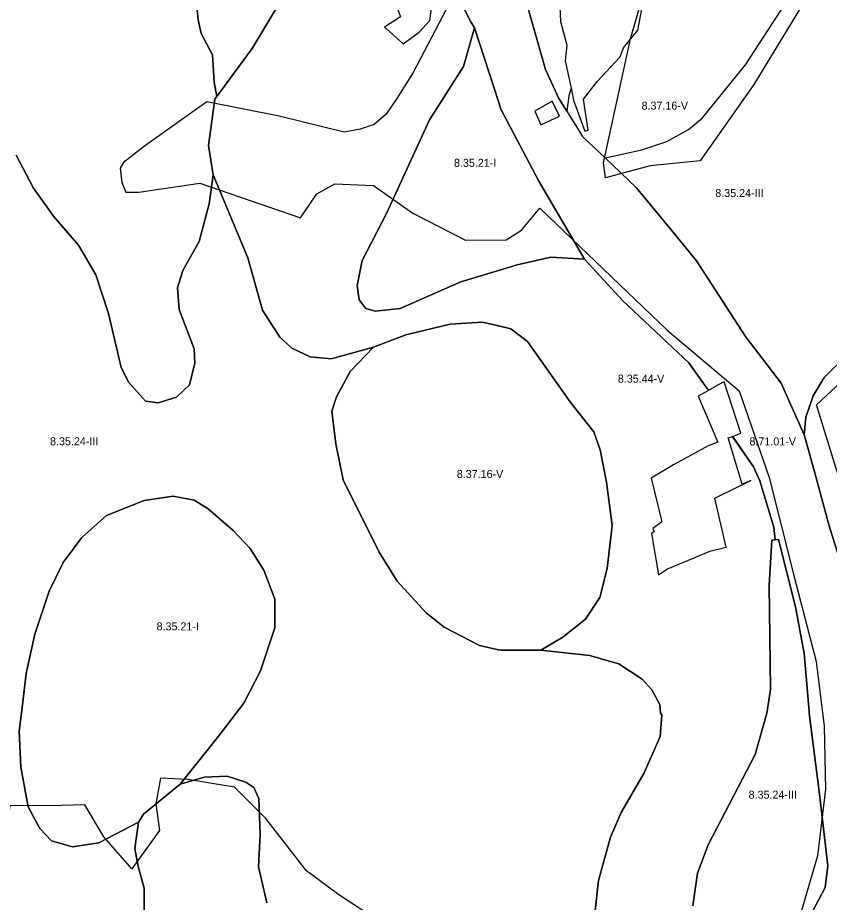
# Model space of a CAD drawing. Extents: x -547623 to -533936, y -1096714 to -1086523.
# Drawn here: x -541850 to -540837, y -1093236 to -1092131 of the extents above; entities that cross this region are included whole.
import ezdxf

# ---------------------------------------------------------------- set-up
doc = ezdxf.new("R2010")
doc.units = 0
for name, color, linetype in [('Vrstva 27', 7, 'Continuous'), ('Vrstva 28', 7, 'Continuous'), ('Vrstva 29', 7, 'Continuous')]:
    doc.layers.add(name, color=color, linetype=linetype)

msp = doc.modelspace()

# ---------------------------------------------------------------- linework, layer by layer
at = {"layer": 'Vrstva 28'}
for p, q in [((-541310.5, -1092085), (-541284.5, -1092136.5)), ((-541629, -1092091), (-541625, -1092134)), ((-541557.5, -1092170), (-541525, -1092116)), ((-541625, -1092134), (-541621, -1092151)), ((-541284.5, -1092136.5), (-541280, -1092144)), ((-541621, -1092151), (-541607, -1092178)), ((-541293.5, -1092192.5), (-541280, -1092144)), ((-541280, -1092144), (-541293.5, -1092192.5)), ((-541280, -1092144), (-541250, -1092236.3)), ((-541601.5, -1092230), (-541557.5, -1092170)), ((-541607, -1092178), (-541605, -1092212)), ((-541336, -1092259), (-541293.5, -1092192.5)), ((-541293.5, -1092192.5), (-541336, -1092259)), ((-541605, -1092212), (-541601.5, -1092230)), ((-541601.5, -1092230), (-541604, -1092233)), ((-541604, -1092233), (-541601.5, -1092230)), ((-541604, -1092233), (-541612, -1092291)), ((-541612, -1092291), (-541604, -1092233)), ((-541250, -1092236.3), (-541247, -1092245.5)), ((-541247, -1092245.5), (-541199.5, -1092335.5)), ((-541389.5, -1092376), (-541336, -1092259)), ((-541336, -1092259), (-541389.5, -1092376)), ((-541612, -1092291), (-541606, -1092327.5)), ((-541606, -1092327.5), (-541612, -1092291)), ((-541830.5, -1092344.5), (-541852, -1092303)), ((-541852, -1092303), (-541830.5, -1092344.5)), ((-541606, -1092327.5), (-541611, -1092364)), ((-541611, -1092364), (-541606, -1092327.5)), ((-541606, -1092327.5), (-541563, -1092431.5)), ((-541563, -1092431.5), (-541606, -1092327.5)), ((-541199.5, -1092335.5), (-541142.5, -1092433)), ((-541805.5, -1092379.5), (-541830.5, -1092344.5)), ((-541830.5, -1092344.5), (-541805.5, -1092379.5)), ((-541611, -1092364), (-541623.5, -1092411)), ((-541623.5, -1092411), (-541611, -1092364)), ((-541774.5, -1092415.5), (-541805.5, -1092379.5)), ((-541805.5, -1092379.5), (-541774.5, -1092415.5)), ((-541420, -1092434.5), (-541389.5, -1092376)), ((-541389.5, -1092376), (-541420, -1092434.5)), ((-541752.5, -1092452.5), (-541774.5, -1092415.5)), ((-541774.5, -1092415.5), (-541752.5, -1092452.5)), ((-541623.5, -1092411), (-541644, -1092447)), ((-541644, -1092447), (-541623.5, -1092411)), ((-541563, -1092431.5), (-541544.5, -1092496.5)), ((-541544.5, -1092496.5), (-541563, -1092431.5)), ((-541426.5, -1092466), (-541420, -1092434.5)), ((-541420, -1092434.5), (-541426.5, -1092466)), ((-541226.5, -1092440), (-541250, -1092447.2)), ((-541250, -1092447.2), (-541226.5, -1092440)), ((-541184.5, -1092430.5), (-541226.5, -1092440)), ((-541226.5, -1092440), (-541184.5, -1092430.5)), ((-541142.5, -1092433), (-541184.5, -1092430.5)), ((-541184.5, -1092430.5), (-541142.5, -1092433)), ((-541142.5, -1092433), (-541095, -1092484.5)), ((-541644, -1092447), (-541650.5, -1092469)), ((-541650.5, -1092469), (-541644, -1092447)), ((-541250, -1092447.2), (-541297, -1092461.5)), ((-541297, -1092461.5), (-541250, -1092447.2)), ((-541737, -1092501), (-541752.5, -1092452.5)), ((-541752.5, -1092452.5), (-541737, -1092501)), ((-541297, -1092461.5), (-541372.5, -1092494.5)), ((-541372.5, -1092494.5), (-541297, -1092461.5)), ((-541650.5, -1092469), (-541648.5, -1092496)), ((-541648.5, -1092496), (-541650.5, -1092469)), ((-541424, -1092484), (-541426.5, -1092466)), ((-541426.5, -1092466), (-541424, -1092484)), ((-541415.5, -1092494.5), (-541424, -1092484)), ((-541424, -1092484), (-541415.5, -1092494.5)), ((-541404, -1092498), (-541415.5, -1092494.5)), ((-541415.5, -1092494.5), (-541404, -1092498)), ((-541372.5, -1092494.5), (-541404, -1092498)), ((-541404, -1092498), (-541372.5, -1092494.5)), ((-541095, -1092484.5), (-541012, -1092562.5)), ((-541721, -1092568.5), (-541737, -1092501)), ((-541737, -1092501), (-541721, -1092568.5)), ((-541648.5, -1092496), (-541630, -1092545)), ((-541630, -1092545), (-541648.5, -1092496)), ((-541544.5, -1092496.5), (-541523, -1092530.5)), ((-541523, -1092530.5), (-541544.5, -1092496.5)), ((-541310, -1092514), (-541365.5, -1092527.5)), ((-541365.5, -1092527.5), (-541310, -1092514)), ((-541270, -1092511.5), (-541310, -1092514)), ((-541310, -1092514), (-541270, -1092511.5)), ((-541250, -1092516.3), (-541270, -1092511.5)), ((-541270, -1092511.5), (-541250, -1092516.3)), ((-541234.5, -1092520), (-541250, -1092516.3)), ((-541250, -1092516.3), (-541234.5, -1092520)), ((-541365.5, -1092527.5), (-541406, -1092543)), ((-541406, -1092543), (-541365.5, -1092527.5)), ((-541213.5, -1092536), (-541234.5, -1092520)), ((-541234.5, -1092520), (-541213.5, -1092536)), ((-541523, -1092530.5), (-541508, -1092544)), ((-541508, -1092544), (-541523, -1092530.5)), ((-541159.5, -1092612.5), (-541213.5, -1092536)), ((-541213.5, -1092536), (-541159.5, -1092612.5)), ((-541630, -1092545), (-541629, -1092563)), ((-541629, -1092563), (-541630, -1092545)), ((-541508, -1092544), (-541485, -1092555)), ((-541485, -1092555), (-541508, -1092544)), ((-541459, -1092557.5), (-541406, -1092543)), ((-541406, -1092543), (-541459, -1092557.5)), ((-541406, -1092543), (-541435, -1092573.5)), ((-541435, -1092573.5), (-541406, -1092543)), ((-541485, -1092555), (-541459, -1092557.5)), ((-541459, -1092557.5), (-541485, -1092555)), ((-540843, -1092581), (-540816, -1092554)), ((-541711.5, -1092587), (-541721, -1092568.5)), ((-541721, -1092568.5), (-541711.5, -1092587)), ((-541629, -1092563), (-541635.5, -1092590)), ((-541635.5, -1092590), (-541629, -1092563)), ((-541012, -1092562.5), (-540987.8, -1092596.9)), ((-541435, -1092573.5), (-541452, -1092605)), ((-541452, -1092605), (-541435, -1092573.5)), ((-540857, -1092603.5), (-540843, -1092581)), ((-541690.5, -1092610.5), (-541711.5, -1092587)), ((-541711.5, -1092587), (-541690.5, -1092610.5)), ((-541635.5, -1092590), (-541652, -1092605.5)), ((-541652, -1092605.5), (-541635.5, -1092590)), ((-541652, -1092605.5), (-541675, -1092612.5)), ((-541675, -1092612.5), (-541652, -1092605.5)), ((-541452, -1092605), (-541458, -1092623)), ((-541458, -1092623), (-541452, -1092605)), ((-540866, -1092630.5), (-540857, -1092603.5)), ((-541675, -1092612.5), (-541690.5, -1092610.5)), ((-541690.5, -1092610.5), (-541675, -1092612.5)), ((-541131, -1092648.5), (-541159.5, -1092612.5)), ((-541159.5, -1092612.5), (-541131, -1092648.5)), ((-541458, -1092623), (-541453, -1092663.5)), ((-541453, -1092663.5), (-541458, -1092623)), ((-540868, -1092652.5), (-540866, -1092630.5)), ((-541123, -1092671), (-541131, -1092648.5)), ((-541131, -1092648.5), (-541123, -1092671)), ((-540957, -1092655.4), (-540931.5, -1092692.5)), ((-540866.8, -1092656.7), (-540868, -1092652.5)), ((-540855.5, -1092697), (-540866.8, -1092656.7)), ((-541453, -1092663.5), (-541444, -1092708.5)), ((-541444, -1092708.5), (-541453, -1092663.5)), ((-541115, -1092711.5), (-541123, -1092671)), ((-541123, -1092671), (-541115, -1092711.5)), ((-540931.5, -1092692.5), (-540923.5, -1092710)), ((-540837, -1092766), (-540855.5, -1092697)), ((-541444, -1092708.5), (-541399, -1092799)), ((-541399, -1092799), (-541444, -1092708.5)), ((-541108, -1092765.5), (-541115, -1092711.5)), ((-541115, -1092711.5), (-541108, -1092765.5)), ((-540923.5, -1092710), (-540906, -1092767.5)), ((-541739.5, -1092753), (-541692.5, -1092734.5)), ((-541692.5, -1092734.5), (-541739.5, -1092753)), ((-541692.5, -1092734.5), (-541656, -1092729)), ((-541656, -1092729), (-541692.5, -1092734.5)), ((-541656, -1092729), (-541630, -1092734)), ((-541630, -1092734), (-541656, -1092729)), ((-541630, -1092734), (-541612.5, -1092745)), ((-541612.5, -1092745), (-541630, -1092734)), ((-541612.5, -1092745), (-541581, -1092772)), ((-541581, -1092772), (-541612.5, -1092745)), ((-541770.5, -1092781), (-541739.5, -1092753)), ((-541739.5, -1092753), (-541770.5, -1092781)), ((-541114, -1092819.5), (-541108, -1092765.5)), ((-541108, -1092765.5), (-541114, -1092819.5)), ((-540906, -1092767.5), (-540904.5, -1092783.6)), ((-540798, -1092891.5), (-540837, -1092766)), ((-541793.5, -1092812), (-541770.5, -1092781)), ((-541770.5, -1092781), (-541793.5, -1092812)), ((-541581, -1092772), (-541560, -1092794.5)), ((-541560, -1092794.5), (-541581, -1092772)), ((-540912, -1092840), (-540908.5, -1092784)), ((-540908.5, -1092784), (-540912, -1092840)), ((-540908.5, -1092784), (-540904.5, -1092783.5)), ((-540904.5, -1092783.5), (-540908.5, -1092784)), ((-540904.5, -1092783.5), (-540900, -1092783)), ((-540900, -1092783), (-540879, -1092867)), ((-541560, -1092794.5), (-541543, -1092821.5)), ((-541543, -1092821.5), (-541560, -1092794.5)), ((-541399, -1092799), (-541376.5, -1092835)), ((-541376.5, -1092835), (-541399, -1092799)), ((-541811, -1092847.5), (-541793.5, -1092812)), ((-541793.5, -1092812), (-541811, -1092847.5)), ((-541543, -1092821.5), (-541529, -1092857.5)), ((-541529, -1092857.5), (-541543, -1092821.5)), ((-541123.5, -1092855.5), (-541114, -1092819.5)), ((-541114, -1092819.5), (-541123.5, -1092855.5)), ((-541376.5, -1092835), (-541340, -1092874.5)), ((-541340, -1092874.5), (-541376.5, -1092835)), ((-541829, -1092901.5), (-541811, -1092847.5)), ((-541811, -1092847.5), (-541829, -1092901.5)), ((-540910, -1092970.5), (-540912, -1092840)), ((-540912, -1092840), (-540910, -1092970.5)), ((-541529, -1092857.5), (-541529, -1092893.5)), ((-541529, -1092893.5), (-541529, -1092857.5)), ((-541141, -1092882.5), (-541123.5, -1092855.5)), ((-541123.5, -1092855.5), (-541141, -1092882.5)), ((-540879, -1092867), (-540868, -1092925.5)), ((-541340, -1092874.5), (-541317.5, -1092892.5)), ((-541317.5, -1092892.5), (-541340, -1092874.5)), ((-541317.5, -1092892.5), (-541273.5, -1092915.5)), ((-541273.5, -1092915.5), (-541317.5, -1092892.5)), ((-541169.5, -1092905), (-541141, -1092882.5)), ((-541141, -1092882.5), (-541169.5, -1092905)), ((-541839.5, -1092950.5), (-541829, -1092901.5)), ((-541829, -1092901.5), (-541839.5, -1092950.5)), ((-541529, -1092893.5), (-541547, -1092947)), ((-541547, -1092947), (-541529, -1092893.5)), ((-541197, -1092921.5), (-541169.5, -1092905)), ((-541169.5, -1092905), (-541197, -1092921.5)), ((-541273.5, -1092915.5), (-541250, -1092920.8)), ((-541250, -1092920.8), (-541273.5, -1092915.5)), ((-541250, -1092920.8), (-541247, -1092921.5)), ((-541247, -1092921.5), (-541250, -1092920.8)), ((-541247, -1092921.5), (-541197, -1092921.5)), ((-541197, -1092921.5), (-541247, -1092921.5)), ((-541197, -1092921.5), (-541136, -1092928)), ((-541136, -1092928), (-541197, -1092921.5)), ((-540868, -1092925.5), (-540862, -1092997.5)), ((-541136, -1092928), (-541099.5, -1092938.5)), ((-541099.5, -1092938.5), (-541136, -1092928)), ((-541547, -1092947), (-541568, -1092987.5)), ((-541568, -1092987.5), (-541547, -1092947)), ((-541099.5, -1092938.5), (-541070.5, -1092957.5)), ((-541070.5, -1092957.5), (-541099.5, -1092938.5)), ((-541845.7, -1093000), (-541839.5, -1092950.5)), ((-541839.5, -1092950.5), (-541845.7, -1093000)), ((-541070.5, -1092957.5), (-541058.5, -1092971)), ((-541058.5, -1092971), (-541070.5, -1092957.5)), ((-540914.7, -1093000), (-540910, -1092970.5)), ((-540910, -1092970.5), (-540914.7, -1093000)), ((-541058.5, -1092971), (-541048.5, -1092989)), ((-541048.5, -1092989), (-541058.5, -1092971)), ((-541568, -1092987.5), (-541577.5, -1093000)), ((-541577.5, -1093000), (-541568, -1092987.5)), ((-541048.5, -1092989), (-541047.5, -1093000)), ((-541047.5, -1093000), (-541048.5, -1092989)), ((-541848.5, -1093022.5), (-541845.7, -1093000)), ((-541845.7, -1093000), (-541848.5, -1093022.5)), ((-541577.5, -1093000), (-541599, -1093028.5)), ((-541599, -1093028.5), (-541577.5, -1093000)), ((-541046, -1093002.5), (-541048, -1093029)), ((-541048, -1093029), (-541046, -1093002.5)), ((-541047.5, -1093000), (-541046, -1093002.5)), ((-541046, -1093002.5), (-541047.5, -1093000)), ((-540929.5, -1093051.5), (-540914.7, -1093000)), ((-540914.7, -1093000), (-540929.5, -1093051.5)), ((-540862, -1092997.5), (-540861.7, -1093000)), ((-540861.7, -1093000), (-540849, -1093101)), ((-541846.5, -1093067.5), (-541848.5, -1093022.5)), ((-541848.5, -1093022.5), (-541846.5, -1093067.5)), ((-541599, -1093028.5), (-541647.5, -1093088.5)), ((-541647.5, -1093088.5), (-541599, -1093028.5)), ((-541048, -1093029), (-541068, -1093074.5)), ((-541068, -1093074.5), (-541048, -1093029)), ((-540988, -1093164.5), (-540929.5, -1093051.5)), ((-540929.5, -1093051.5), (-540988, -1093164.5)), ((-541837, -1093117), (-541846.5, -1093067.5)), ((-541846.5, -1093067.5), (-541837, -1093117)), ((-541617.5, -1093080), (-541647.5, -1093088.5)), ((-541647.5, -1093088.5), (-541617.5, -1093080)), ((-541588.5, -1093078.5), (-541617.5, -1093080)), ((-541617.5, -1093080), (-541588.5, -1093078.5)), ((-541565.5, -1093086), (-541588.5, -1093078.5)), ((-541588.5, -1093078.5), (-541565.5, -1093086)), ((-541068, -1093074.5), (-541096.5, -1093124)), ((-541096.5, -1093124), (-541068, -1093074.5)), ((-541647.5, -1093088.5), (-541693, -1093126)), ((-541693, -1093126), (-541647.5, -1093088.5)), ((-541555.5, -1093093), (-541565.5, -1093086)), ((-541565.5, -1093086), (-541555.5, -1093093)), ((-541549, -1093106.5), (-541555.5, -1093093)), ((-541555.5, -1093093), (-541549, -1093106.5)), ((-540849, -1093101), (-540838.5, -1093190.5)), ((-541547.5, -1093151.5), (-541549, -1093106.5)), ((-541549, -1093106.5), (-541547.5, -1093151.5)), ((-541822.5, -1093144), (-541837, -1093117)), ((-541837, -1093117), (-541822.5, -1093144)), ((-541096.5, -1093124), (-541110, -1093155)), ((-541110, -1093155), (-541096.5, -1093124)), ((-541699.5, -1093136), (-541749, -1093162)), ((-541749, -1093162), (-541699.5, -1093136)), ((-541699.5, -1093136), (-541704, -1093169)), ((-541704, -1093169), (-541699.5, -1093136)), ((-541693, -1093126), (-541699.5, -1093136)), ((-541699.5, -1093136), (-541693, -1093126)), ((-541808, -1093159.5), (-541822.5, -1093144)), ((-541822.5, -1093144), (-541808, -1093159.5)), ((-541549.5, -1093192), (-541547.5, -1093151.5)), ((-541547.5, -1093151.5), (-541549.5, -1093192)), ((-541110, -1093155), (-541125, -1093209)), ((-541125, -1093209), (-541110, -1093155)), ((-541782, -1093167), (-541808, -1093159.5)), ((-541808, -1093159.5), (-541782, -1093167)), ((-541749, -1093162), (-541782, -1093167)), ((-541782, -1093167), (-541749, -1093162)), ((-541704, -1093169), (-541700, -1093191.5)), ((-541700, -1093191.5), (-541704, -1093169)), ((-541001.5, -1093200), (-540988, -1093164.5)), ((-540988, -1093164.5), (-541001.5, -1093200)), ((-540838.5, -1093190.5), (-540842, -1093217.5)), ((-541700, -1093191.5), (-541692.5, -1093218.5)), ((-541692.5, -1093218.5), (-541700, -1093191.5)), ((-541539, -1093237), (-541549.5, -1093192)), ((-541549.5, -1093192), (-541539, -1093237)), ((-541007, -1093240.5), (-541001.5, -1093200)), ((-541001.5, -1093200), (-541007, -1093240.5)), ((-541125, -1093209), (-541133, -1093280.5)), ((-541133, -1093280.5), (-541125, -1093209)), ((-541692.5, -1093218.5), (-541692.5, -1093259)), ((-541692.5, -1093259), (-541692.5, -1093218.5)), ((-540842, -1093217.5), (-540901, -1093330))]:
    msp.add_line(p, q, dxfattribs=at)
for points in [[(-541325, -1092027.3), (-541382.1, -1092029.9), (-541401.5, -1092051.3), (-541372.3, -1092130.2), (-541392, -1092143.1), (-541390, -1092144.9), (-541368.7, -1092164), (-541349.1, -1092149.6), (-541335.6, -1092135.1), (-541332.8, -1092113.8), (-541334.3, -1092107.7), (-541320.2, -1092097.8), (-541313.2, -1092064.2), (-541308.1, -1092026.5), (-541325, -1092027.3)], [(-540990.6, -1092592.9), (-541012, -1092562.5), (-541095, -1092484.5), (-541142.5, -1092433), (-541199.5, -1092335.5), (-541247, -1092245.5), (-541250, -1092236.3), (-541280, -1092144), (-541284.5, -1092136.5), (-541310.5, -1092085), (-541315, -1092072.5)], [(-540816, -1092554), (-540843, -1092581), (-540857, -1092603.5), (-540866, -1092630.5), (-540868, -1092652.5), (-540897, -1092588), (-540941.5, -1092529.5), (-541002.5, -1092435), (-541032, -1092399), (-541078, -1092343.5), (-541116.5, -1092306.5), (-541071, -1092296.5), (-541039.5, -1092286), (-541012.5, -1092271), (-540995, -1092256.5), (-540941.5, -1092190.5), (-540895.5, -1092120), (-540873.5, -1092090), (-540869.1, -1092084.1)], [(-541852, -1092303), (-541830.5, -1092344.5), (-541805.5, -1092379.5), (-541774.5, -1092415.5), (-541752.5, -1092452.5), (-541737, -1092501), (-541721, -1092568.5), (-541711.5, -1092587), (-541690.5, -1092610.5), (-541675, -1092612.5), (-541652, -1092605.5), (-541635.5, -1092590), (-541629, -1092563), (-541630, -1092545), (-541648.5, -1092496), (-541650.5, -1092469), (-541644, -1092447), (-541623.5, -1092411), (-541611, -1092364), (-541606, -1092327.5), (-541612, -1092291), (-541604, -1092233), (-541601.5, -1092230), (-541605, -1092212), (-541607, -1092178), (-541621, -1092151), (-541625, -1092134), (-541629, -1092091)], [(-541525, -1092116), (-541557.5, -1092170), (-541601.5, -1092230), (-541605, -1092212), (-541607, -1092178), (-541621, -1092151), (-541625, -1092134), (-541629, -1092091)], [(-541218, -1092102), (-541191, -1092196), (-541174.5, -1092232.5), (-541164.5, -1092248), (-541145, -1092280), (-541116.5, -1092306.5), (-541078, -1092343.5), (-541032, -1092399), (-541002.5, -1092435), (-540941.5, -1092529.5), (-540897, -1092588), (-540868, -1092652.5), (-540866.8, -1092656.7), (-540855.5, -1092697), (-540837, -1092766), (-540798, -1092891.5)], [(-541159.3, -1092219.4), (-541162, -1092229), (-541164.5, -1092248), (-541174.5, -1092232.5), (-541191, -1092196), (-541218, -1092102)], [(-541173.1, -1092118.4), (-541172.6, -1092136.1), (-541164.6, -1092165.6), (-541166.8, -1092185.2), (-541159.3, -1092219.4)], [(-541159.3, -1092219.4), (-541156, -1092234.4), (-541142.1, -1092273.3), (-541137.7, -1092272.1), (-541143.6, -1092233.3), (-541126.5, -1092211.1), (-541097.9, -1092180.2), (-541093.8, -1092168.9), (-541075.8, -1092147.2), (-541070.9, -1092120.8), (-541068.1, -1092120.7)], [(-541336, -1092259), (-541389.5, -1092376), (-541420, -1092434.5), (-541426.5, -1092466), (-541424, -1092484), (-541415.5, -1092494.5), (-541404, -1092498), (-541372.5, -1092494.5), (-541297, -1092461.5), (-541250, -1092447.2), (-541226.5, -1092440), (-541184.5, -1092430.5), (-541142.5, -1092433), (-541199.5, -1092335.5), (-541247, -1092245.5), (-541250, -1092236.3), (-541280, -1092144), (-541293.5, -1092192.5), (-541336, -1092259)], [(-541197.1, -1092265.4), (-541173.8, -1092254.6), (-541182.9, -1092235.8), (-541204.6, -1092248.2), (-541197.1, -1092265.4)], [(-541133, -1093280.5), (-541125, -1093209), (-541110, -1093155), (-541096.5, -1093124), (-541068, -1093074.5), (-541048, -1093029), (-541046, -1093002.5), (-541047.5, -1093000), (-541048.5, -1092989), (-541058.5, -1092971), (-541070.5, -1092957.5), (-541099.5, -1092938.5), (-541136, -1092928), (-541197, -1092921.5), (-541247, -1092921.5), (-541250, -1092920.8), (-541273.5, -1092915.5), (-541317.5, -1092892.5), (-541340, -1092874.5), (-541376.5, -1092835), (-541399, -1092799), (-541444, -1092708.5), (-541453, -1092663.5), (-541458, -1092623), (-541452, -1092605), (-541435, -1092573.5), (-541406, -1092543), (-541459, -1092557.5), (-541485, -1092555), (-541508, -1092544), (-541523, -1092530.5), (-541544.5, -1092496.5), (-541563, -1092431.5), (-541606, -1092327.5), (-541611, -1092364), (-541623.5, -1092411), (-541644, -1092447), (-541650.5, -1092469), (-541648.5, -1092496), (-541630, -1092545), (-541629, -1092563), (-541635.5, -1092590), (-541652, -1092605.5), (-541675, -1092612.5), (-541690.5, -1092610.5), (-541711.5, -1092587), (-541721, -1092568.5), (-541737, -1092501), (-541752.5, -1092452.5), (-541774.5, -1092415.5), (-541805.5, -1092379.5), (-541830.5, -1092344.5), (-541852, -1092303)], [(-541444, -1092708.5), (-541399, -1092799), (-541376.5, -1092835), (-541340, -1092874.5), (-541317.5, -1092892.5), (-541273.5, -1092915.5), (-541250, -1092920.8), (-541247, -1092921.5), (-541197, -1092921.5), (-541169.5, -1092905), (-541141, -1092882.5), (-541123.5, -1092855.5), (-541114, -1092819.5), (-541108, -1092765.5), (-541115, -1092711.5), (-541123, -1092671), (-541131, -1092648.5), (-541159.5, -1092612.5), (-541213.5, -1092536), (-541234.5, -1092520), (-541250, -1092516.3), (-541270, -1092511.5), (-541310, -1092514), (-541365.5, -1092527.5), (-541406, -1092543), (-541435, -1092573.5), (-541452, -1092605), (-541458, -1092623), (-541453, -1092663.5), (-541444, -1092708.5)], [(-540816, -1092554), (-540843, -1092581), (-540857, -1092603.5), (-540866, -1092630.5), (-540868, -1092652.5), (-540866.8, -1092656.7), (-540855.5, -1092697), (-540837, -1092766), (-540798, -1092891.5)], [(-540987.8, -1092596.9), (-541000.5, -1092603.9), (-540976, -1092661.4), (-540988, -1092666.2), (-541031.4, -1092689.9), (-541059.4, -1092706.7), (-541045.9, -1092761.2), (-541057.3, -1092769.3), (-541055.5, -1092773.3), (-541058.8, -1092775.5), (-541050.2, -1092827.4), (-541038.9, -1092819.7), (-541005.4, -1092805.9), (-540986.1, -1092797.5), (-540965.5, -1092792.8), (-540979.5, -1092731.5), (-540934.9, -1092709.6), (-540945.7, -1092713.8), (-540963.2, -1092656.3), (-540957.8, -1092654.3), (-540947.2, -1092650.4), (-540968.2, -1092586.2), (-540970.8, -1092587.6), (-540987.8, -1092596.9)], [(-540955.3, -1093427.9), (-540920.5, -1093360.5), (-540901, -1093330), (-540842, -1093217.5), (-540838.5, -1093190.5), (-540849, -1093101), (-540861.7, -1093000), (-540862, -1092997.5), (-540868, -1092925.5), (-540879, -1092867), (-540900, -1092783), (-540904.5, -1092783.5), (-540906, -1092767.5), (-540923.5, -1092710), (-540931.5, -1092692.5), (-540957.9, -1092654.2)], [(-541647.5, -1093088.5), (-541599, -1093028.5), (-541577.5, -1093000), (-541568, -1092987.5), (-541547, -1092947), (-541529, -1092893.5), (-541529, -1092857.5), (-541543, -1092821.5), (-541560, -1092794.5), (-541581, -1092772), (-541612.5, -1092745), (-541630, -1092734), (-541656, -1092729), (-541692.5, -1092734.5), (-541739.5, -1092753), (-541770.5, -1092781), (-541793.5, -1092812), (-541811, -1092847.5), (-541829, -1092901.5), (-541839.5, -1092950.5), (-541845.7, -1093000), (-541848.5, -1093022.5), (-541846.5, -1093067.5), (-541837, -1093117), (-541822.5, -1093144), (-541808, -1093159.5), (-541782, -1093167), (-541749, -1093162), (-541699.5, -1093136), (-541693, -1093126), (-541647.5, -1093088.5)], [(-541692.5, -1093259), (-541692.5, -1093218.5), (-541700, -1093191.5), (-541704, -1093169), (-541699.5, -1093136), (-541749, -1093162), (-541782, -1093167), (-541808, -1093159.5), (-541822.5, -1093144), (-541837, -1093117), (-541846.5, -1093067.5), (-541848.5, -1093022.5), (-541845.7, -1093000), (-541839.5, -1092950.5), (-541829, -1092901.5), (-541811, -1092847.5), (-541793.5, -1092812), (-541770.5, -1092781), (-541739.5, -1092753), (-541692.5, -1092734.5), (-541656, -1092729), (-541630, -1092734), (-541612.5, -1092745), (-541581, -1092772), (-541560, -1092794.5), (-541543, -1092821.5), (-541529, -1092857.5), (-541529, -1092893.5), (-541547, -1092947), (-541568, -1092987.5), (-541577.5, -1093000), (-541599, -1093028.5), (-541647.5, -1093088.5), (-541617.5, -1093080), (-541588.5, -1093078.5), (-541565.5, -1093086), (-541555.5, -1093093), (-541549, -1093106.5), (-541547.5, -1093151.5), (-541549.5, -1093192), (-541539, -1093237)], [(-541539, -1093237), (-541549.5, -1093192), (-541547.5, -1093151.5), (-541549, -1093106.5), (-541555.5, -1093093), (-541565.5, -1093086), (-541588.5, -1093078.5), (-541617.5, -1093080), (-541647.5, -1093088.5), (-541693, -1093126), (-541699.5, -1093136), (-541704, -1093169), (-541700, -1093191.5), (-541692.5, -1093218.5), (-541692.5, -1093259)]]:
    msp.add_lwpolyline(points, dxfattribs=at)
at = {"layer": 'Vrstva 29'}
for points in [[(-540831.9, -1092051.7), (-540931.1, -1092214.7), (-540998.1, -1092310.1), (-541060.5, -1092316.4), (-541116.4, -1092331.6), (-541118.9, -1092312.6), (-541084.4, -1092156.3), (-541051.2, -1092041.6)], [(-541310.5, -1092112.4), (-541356.4, -1092199.9), (-541376.6, -1092232.5), (-541390.3, -1092252), (-541405.2, -1092264.7), (-541422.5, -1092270.5), (-541442.4, -1092274.3), (-541523.9, -1092254.6), (-541614.1, -1092236.6), (-541692.1, -1092291.9), (-541718.1, -1092312.1), (-541722.2, -1092319.3), (-541720.3, -1092337.2), (-541715.2, -1092349.3), (-541698.9, -1092349.5), (-541622.9, -1092338.1), (-541497.3, -1092381.2), (-541476.9, -1092351.4), (-541454.3, -1092338.8), (-541406.1, -1092341), (-541356.7, -1092375.5), (-541291.2, -1092409.1), (-541240.3, -1092409), (-541221.3, -1092396.7), (-541198.1, -1092369.3), (-541039.1, -1092521.5), (-540949.4, -1092597.6), (-540911.8, -1092705.7), (-540881.1, -1092828.1), (-540853.2, -1092935.4), (-540843.3, -1093016.1), (-540841.6, -1093094.7), (-540851.5, -1093178.1), (-540878.9, -1093272.2)], [(-540784.8, -1092834.8), (-540852.7, -1092614.8), (-540816, -1092580.9)], [(-541540.3, -1093131.5), (-541579.6, -1093092.6), (-541637.9, -1093082.7), (-541672, -1093081), (-541677.8, -1093113.2), (-541673.1, -1093146.7), (-541707.9, -1093194.2), (-541742.5, -1093154.3), (-541766.3, -1093114.3), (-541810.5, -1093115.9), (-541860.1, -1093115.3), (-541864.2, -1093149), (-541872.1, -1093183.4), (-541890.4, -1093226.3), (-541916.5, -1093254.9)], [(-541399.9, -1093259.2), (-541449.4, -1093226.7), (-541489.4, -1093197), (-541540.3, -1093131.5)]]:
    msp.add_lwpolyline(points, dxfattribs=at)

# ---------------------------------------------------------------- texts
at = {"layer": 'Vrstva 27'}
for s, p in [('8.37.16-V', (-541071.2, -1092246.3)), ('8.35.21-I', (-541305.4, -1092317.7)), ('8.35.24-III', (-540979.1, -1092355.4)), ('8.35.44-V', (-541100.8, -1092587.3)), ('8.35.24-III', (-541809.8, -1092665.4)), ('8.71.01-V', (-540936.4, -1092665.6)), ('8.37.16-V', (-541301.9, -1092706.3)), ('8.35.21-I', (-541676.8, -1092896.6)), ('8.35.24-III', (-540937.5, -1093106.8))]:
    msp.add_text(s, height=10, dxfattribs=at).set_placement(p)

doc.saveas('drawing.dxf')
